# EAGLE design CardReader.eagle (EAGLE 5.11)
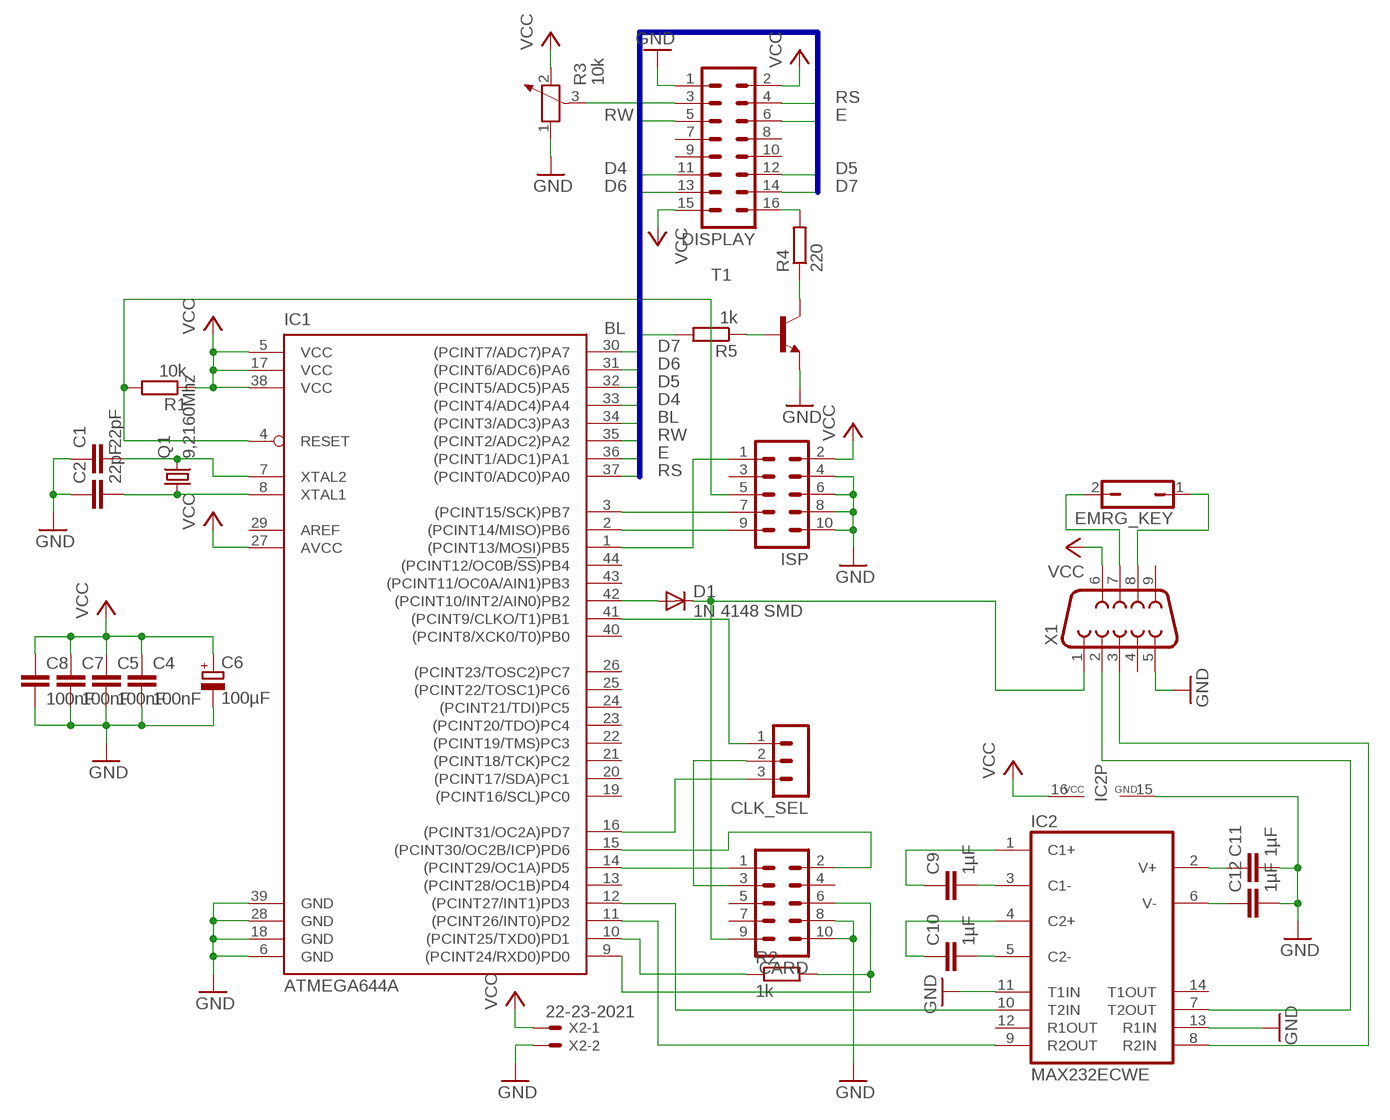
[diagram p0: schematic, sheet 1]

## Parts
C1  22pF  C-EUC0603  [C0603]
C2  22pF  C-EUC0603  [C0603]
C4  100nF  C-EUC0603  [C0603]
C5  100nF  C-EUC0603  [C0603]
C6  100µF  CPOL-EUE2.5-7  [E2,5-7]
C7  100nF  C-EUC0603  [C0603]
C8  100nF  C-EUC0603  [C0603]
C9  1µF  C-EUC0603  [C0603]
C10  1µF  C-EUC0603  [C0603]
C11  1µF  C-EUC0603  [C0603]
C12  1µF  C-EUC0603  [C0603]
CARD  ML10  [ML10]
CLK_SEL  MA03-1  [MA03-1]
D1  1N 4148 SMD  DIODE-MINIMELF  [MINIMELF]
DISPLAY  ML16  [ML16]
EMRG_KEY  JP1Q  [JP1]
IC1  ATMEGA644A  [TQFP44]
IC2  MAX232ECWE  [SO16L]
ISP  ML10  [ML10]
Q1  9,2160Mhz  CRYSTALHC49U-V  [HC49U-V]
R1  10k  R-EU_R0603  [R0603]
R2  1k  R-EU_R0603  [R0603]
R3  10k  POTENTIOMETER_PT-10S  [PT-10S]
R4  220  R-EU_R0603  [R0603]
R5  1k  R-EU_R0603  [R0603]
T1  -NPN-TO92  [TO92]
X1  F09H  [F09H]
X2  22-23-2021  [22-23-2021]

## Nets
BL: IC1.34((PCINT3/ADC3)PA3) R5.2
D4: DISPLAY.11 IC1.33((PCINT4/ADC4)PA4)
D5: DISPLAY.12 IC1.32((PCINT5/ADC5)PA5)
D6: DISPLAY.13 IC1.31((PCINT6/ADC6)PA6)
D7: DISPLAY.14 IC1.30((PCINT7/ADC7)PA7)
E: DISPLAY.6 IC1.36((PCINT1/ADC1)PA1)
GND: C1.1 C2.1 C4.2 C5.2 C6.- C7.2 C8.2 C11.2 C12.2 CARD.8 CARD.10 DISPLAY.1 IC1.6(GND) IC1.18(GND) IC1.28(GND) IC1.39(GND) IC2.11(T1IN) IC2.13(R1IN) IC2.15(GND) ISP.4 ISP.6 ISP.8 ISP.10 R3.1 T1.1(E) X1.5 X2.2
N$1: IC1.4(RESET) ISP.5 R1.2
N$2: C9.2 IC2.3(C1-)
N$3: C9.1 IC2.1(C1+)
N$4: C2.2 IC1.8(XTAL1) Q1.1
N$5: C1.2 IC1.7(XTAL2) Q1.2
N$6: C10.2 IC2.5(C2-)
N$7: C10.1 IC2.4(C2+)
N$8: C11.1 IC2.2(V+)
N$9: C12.1 IC2.6(V-)
N$10: IC1.1((PCINT13/MOSI)PB5) ISP.1
N$11: IC1.3((PCINT15/SCK)PB7) ISP.7
N$12: IC1.2((PCINT14/MISO)PB6) ISP.9
N$13: CARD.9 D1.C X1.1
N$14: CLK_SEL.1 IC1.41((PCINT9/CLKO/T1)PB1)
N$15: CARD.1 IC1.14((PCINT29/OC1A)PD5)
N$16: CARD.2 IC1.15((PCINT30/OC2B/ICP)PD6)
N$17: D1.A IC1.42((PCINT10/INT2/AIN0)PB2)
N$18: CARD.6 IC1.9((PCINT24/RXD0)PD0) R2.2
N$19: CLK_SEL.3 IC1.16((PCINT31/OC2A)PD7)
N$20: CARD.3 CLK_SEL.2
N$21: DISPLAY.3 R3.3
N$22: R5.1 T1.2(B)
N$23: R4.1 T1.3(C)
N$24: DISPLAY.16 R4.2
N$25: IC1.11((PCINT26/INT0)PD2) IC2.9(R2OUT)
N$26: IC1.12((PCINT27/INT1)PD3) IC2.10(T2IN)
N$27: EMRG_KEY.1 X1.8
N$28: EMRG_KEY.2 X1.7
N$29: IC2.8(R2IN) X1.3
N$30: IC2.7(T2OUT) X1.2
N$31: IC1.10((PCINT25/TXD0)PD1) R2.1
RS: DISPLAY.4 IC1.37((PCINT0/ADC0)PA0)
RW: DISPLAY.5 IC1.35((PCINT2/ADC2)PA2)
VCC: C4.1 C5.1 C6.+ C7.1 C8.1 DISPLAY.2 DISPLAY.15 IC1.5(VCC) IC1.17(VCC) IC1.27(AVCC) IC1.38(VCC) IC2.16(VCC) ISP.2 R1.1 R3.2 X1.6 X2.1
Unconnected: CARD.4 CARD.5 CARD.7 DISPLAY.7 DISPLAY.8 DISPLAY.9 DISPLAY.10 IC1.13((PCINT28/OC1B)PD4) IC1.19((PCINT16/SCL)PC0) IC1.20((PCINT17/SDA)PC1) IC1.21((PCINT18/TCK)PC2) IC1.22((PCINT19/TMS)PC3) IC1.23((PCINT20/TDO)PC4) IC1.24((PCINT21/TDI)PC5) IC1.25((PCINT22/TOSC1)PC6) IC1.26((PCINT23/TOSC2)PC7) IC1.29(AREF) IC1.40((PCINT8/XCK0/T0)PB0) IC1.43((PCINT11/OC0A/AIN1)PB3) IC1.44((PCINT12/OC0B/!SS!)PB4) IC2.12(R1OUT) IC2.14(T1OUT) ISP.3 X1.4 X1.9

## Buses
DISPLAY:D[0..7],E,RS,RW,BL

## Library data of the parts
C1 C2 C4 C5 C7-C12 = rcl:C-EU: CAPACITOR, European symbol
C6 = rcl:CPOL-EU: POLARIZED CAPACITOR, European symbol
CARD ISP = con-harting-ml:ML10: HARTING; OC_FARNELL: unknown; OC_NEWARK: unknown
CLK_SEL = con-lstb:MA03-1: PIN HEADER; OC_FARNELL: unknown; OC_NEWARK: unknown
D1 = diode:DIODE-: DIODE
DISPLAY = con-harting-ml:ML16: HARTING; OC_FARNELL: unknown; OC_NEWARK: unknown
EMRG_KEY = jumper:JP1Q: JUMPER
IC1 = atmel:ATMEGA644: 8-bit Microcontroller with 64K Bytes In-System Programmable Flash Source: http://www.atmel.com/dyn/resources/prod_documents/doc2593.pdf; MPN: ATMEGA644PV-10AU; OC_FARNELL: 1455123; OC_NEWARK: 58M3748
IC2 = maxim:MAX232ECWE: RS232 TRANSEIVER; MF: MAXIM; MPN: MAX232ECWE+; OC_FARNELL: 9724435; OC_NEWARK: 67K4440
Q1 = crystal:CRYSTAL: CRYSTAL; OC_FARNELL: 1666969; OC_NEWARK: unknown
R1 R2 R4 R5 = rcl:R-EU_: RESISTOR, European symbol
R3 = rcl:POTENTIOMETER_: Potentiometer
T1 = transistor:*-NPN-: NPN Transistror BF959 corrected 2008.03.06
X1 = con-subd:F09: SUB-D; OC_FARNELL: unknown; OC_NEWARK: unknown
X2 = con-molex:22-23-2021: .100" (2.54mm) Center Header - 2 Pin; MF: MOLEX; MPN: 22-23-2021; OC_FARNELL: 1462926; OC_NEWARK: 25C3832

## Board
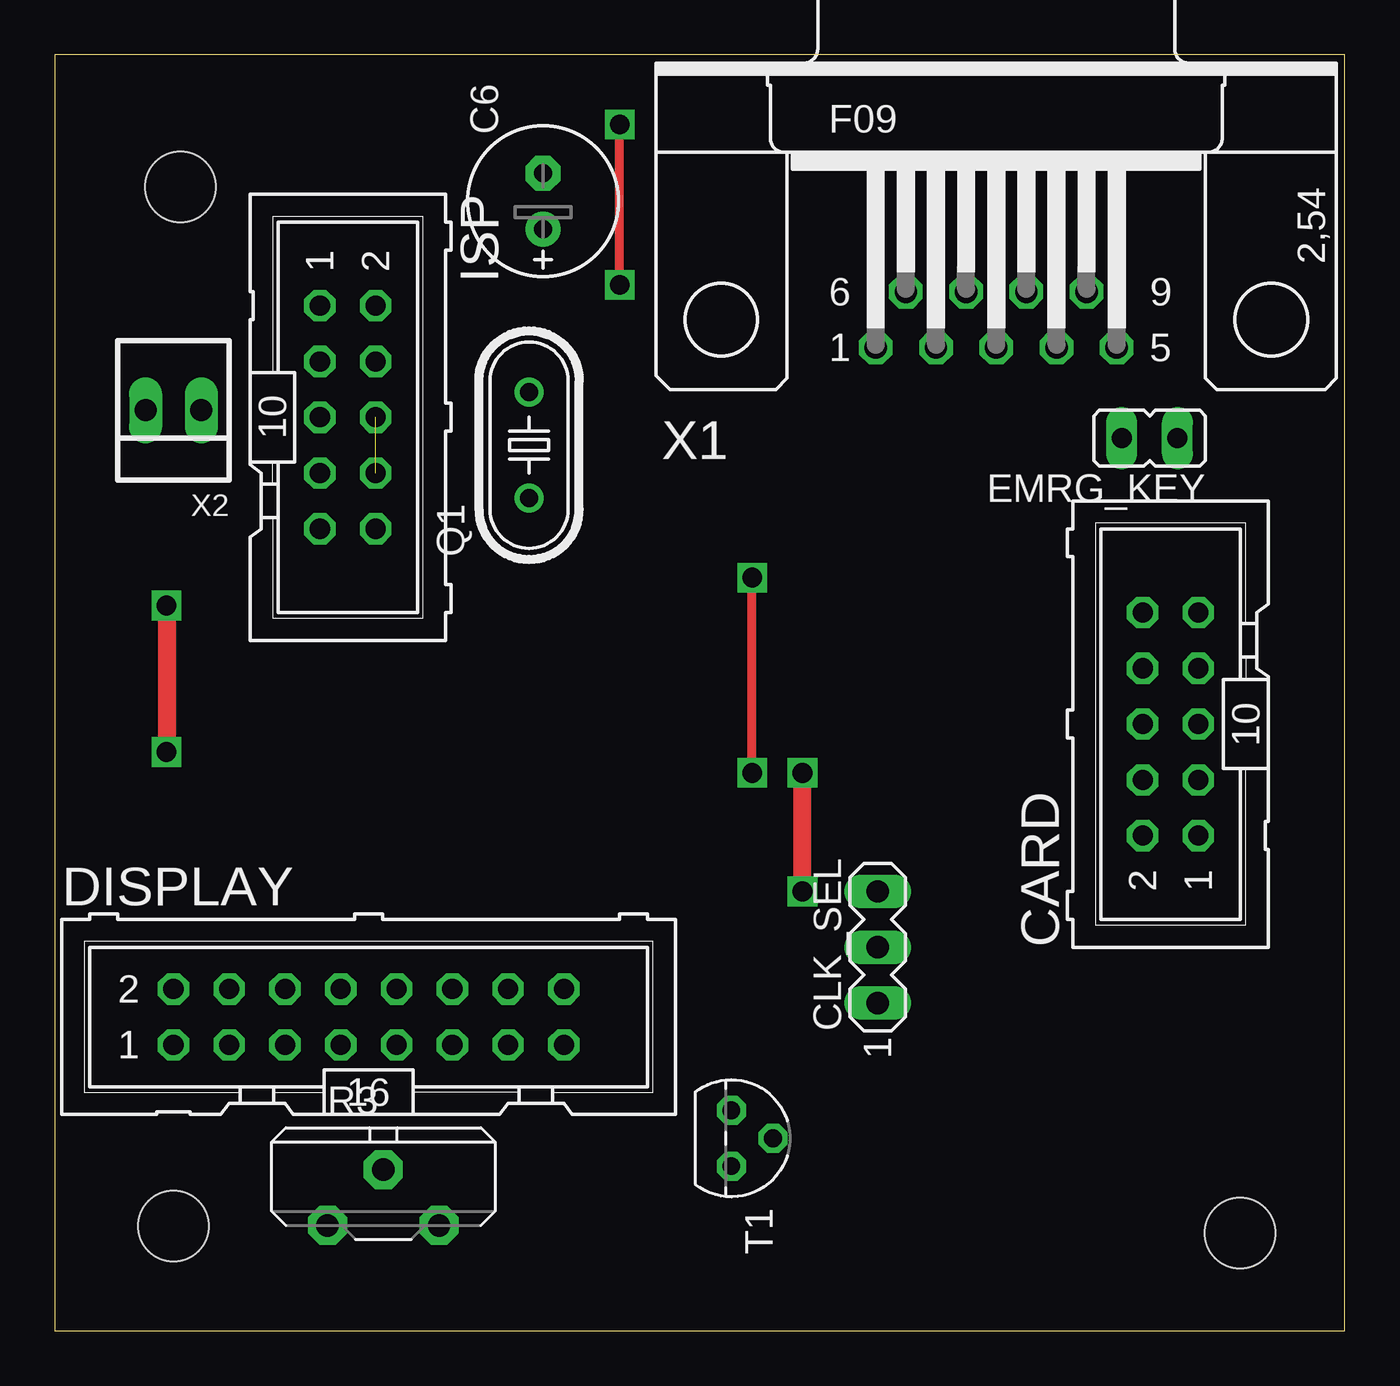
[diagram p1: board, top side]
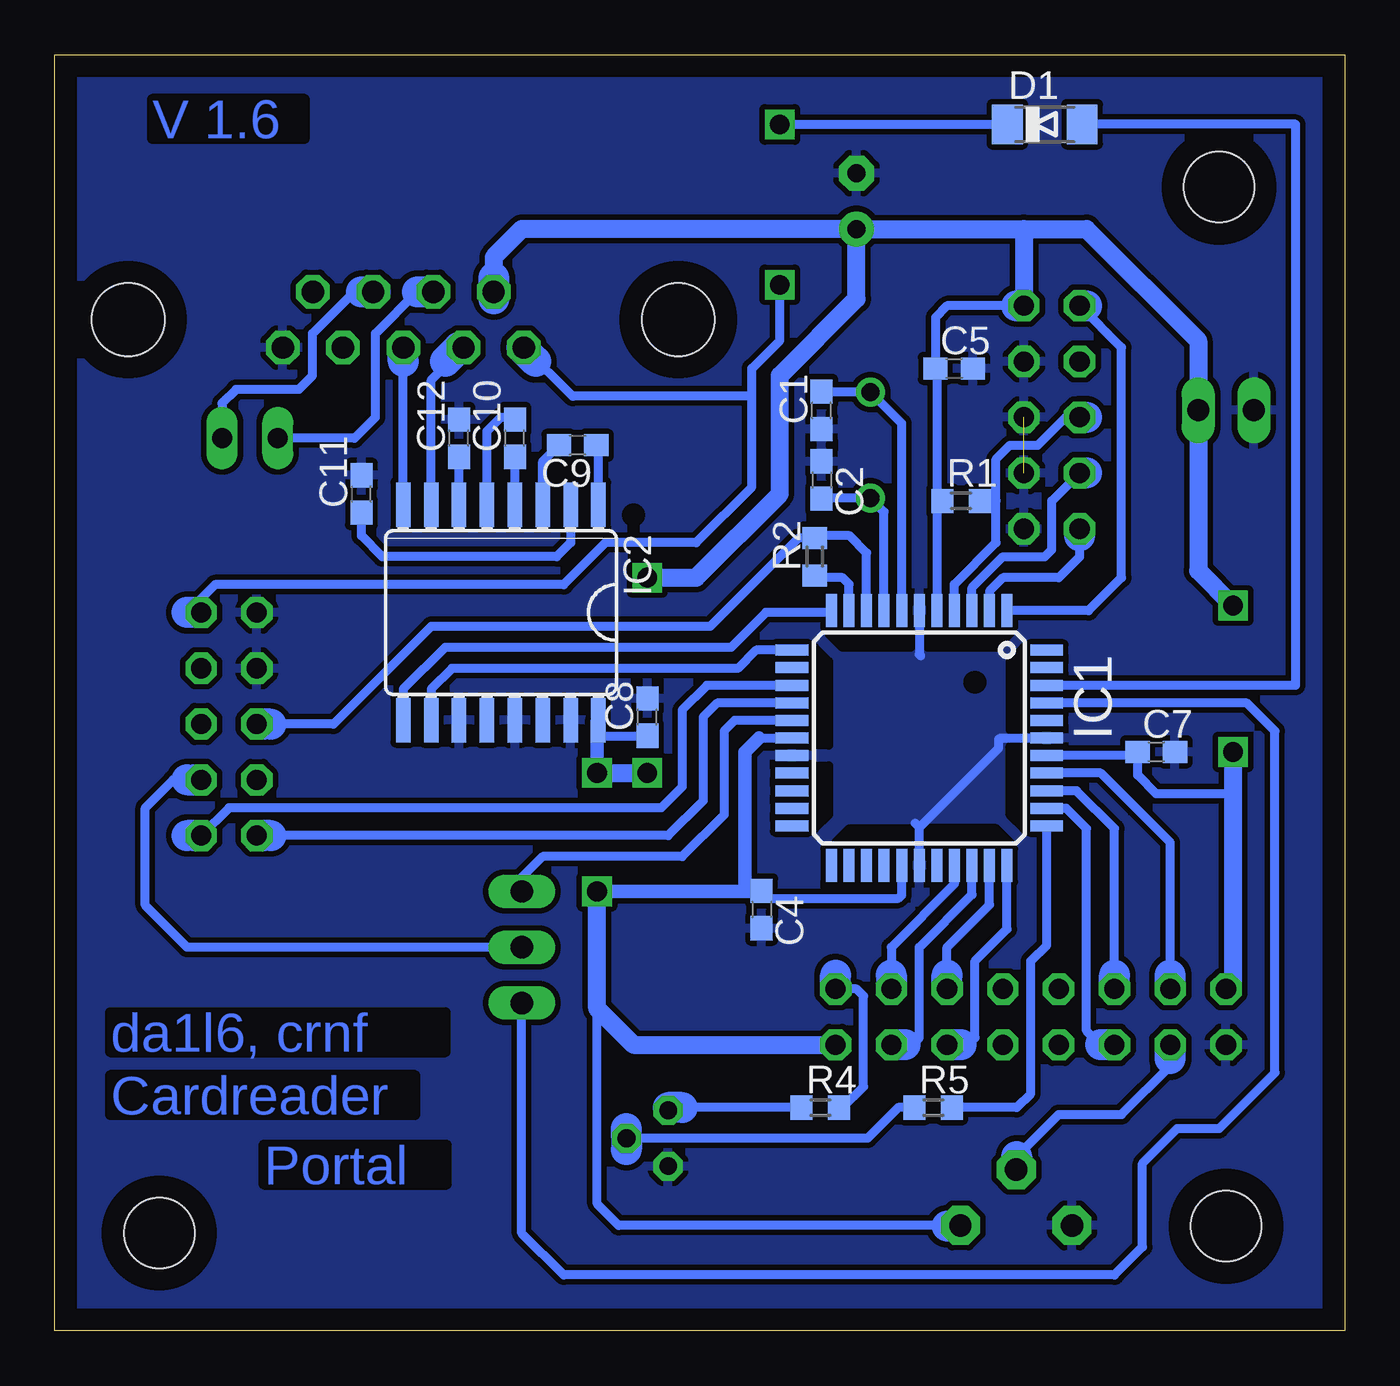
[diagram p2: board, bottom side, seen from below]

Size 58.73 x 58.09 mm. Coordinates in mm from the lower left corner, seen from the top.
Outline: 0,0 58.73,0 58.73,58.09 0,58.09 0,0
Copper layers (1*16): Top 0.035mm / dielectric 1.5mm / Bottom 0.035mm
Design rules "Bilex DRU": minimum track width 10mil, minimum drill 24mil, track to track 10mil, track to pad 10mil, pad to pad 10mil, via to via 10mil, smd to smd 10mil, copper to edge 40mil, drill to drill 8mil, minimum pad ring 10mil, minimum via ring 8mil, stop-mask expansion 4mil, vias tented up to drill 0mil, thermal gap 10mil
Holes 3.2 mm at 5.71,52.07 53.98,4.45 5.4,4.76
bRestrict: area 16.5,29.2 to 17.1,29.8; area 32.1,36.8 to 32.7,37.5; area 23.5,26.7 to 24.1,31.1; area 23.5,22.9 to 24.1,25.7; area 19.7,22.2 to 23.2,22.9; area 15.2,22.2 to 19,22.9; area 14.6,22.9 to 15.2,26.6; area 14.6,27.4 to 15.2,31.1; area 15.2,31.1 to 19,31.8; area 19.7,31.1 to 23.5,31.8

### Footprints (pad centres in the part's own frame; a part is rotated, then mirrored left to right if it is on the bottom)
C0603 = smd 1.1 x 1: 1 -0.85,0; 2 0.85,0
E2,5-7 = drill 0.813 pad 1.6 round: + -1.27,0 | drill 0.813 pad 1.6 octagon: - 1.27,0
ML10 = drill 0.914 octagon: 1 -5.08,-1.27; 2 -5.08,1.27; 3 -2.54,-1.27; 4 -2.54,1.27; 5 0,-1.27; 6 0,1.27; 7 2.54,-1.27; 8 2.54,1.27; 9 5.08,-1.27; 10 5.08,1.27
MA03-1 = drill 1.016 long: 1 -2.54,0; 2 0,0; 3 2.54,0
MINIMELF = smd 1.4 x 1.8: A 1.7,0; C -1.7,0
ML16 = drill 0.914 octagon: 1 -8.89,-1.27; 2 -8.89,1.27; 3 -6.35,-1.27; 4 -6.35,1.27; 5 -3.81,-1.27; 6 -3.81,1.27; 7 -1.27,-1.27; 8 -1.27,1.27; 9 1.27,-1.27; 10 1.27,1.27; 11 3.81,-1.27; 12 3.81,1.27; 13 6.35,-1.27; 14 6.35,1.27; 15 8.89,-1.27; 16 8.89,1.27
JP1 = drill 0.914 long: 1 0,-1.27; 2 0,1.27
TQFP44 = smd 1.5 x 0.5: 1 -5.8,4; 2 -5.8,3.2; 3 -5.8,2.4; 4 -5.8,1.6; 5 -5.8,0.8; 6 -5.8,0; 7 -5.8,-0.8; 8 -5.8,-1.6; 9 -5.8,-2.4; 10 -5.8,-3.2; 11 -5.8,-4; 23 5.8,-4; 24 5.8,-3.2; 25 5.8,-2.4; 26 5.8,-1.6; 27 5.8,-0.8; 28 5.8,0; 29 5.8,0.8; 30 5.8,1.6; 31 5.8,2.4; 32 5.8,3.2; 33 5.8,4 | smd 0.5 x 1.5: 12 -4,-5.8; 13 -3.2,-5.8; 14 -2.4,-5.8; 15 -1.6,-5.8; 16 -0.8,-5.8; 17 0,-5.8; 18 0.8,-5.8; 19 1.6,-5.8; 20 2.4,-5.8; 21 3.2,-5.8; 22 4,-5.8; 34 4,5.8; 35 3.2,5.8; 36 2.4,5.8; 37 1.6,5.8; 38 0.8,5.8; 39 0,5.8; 40 -0.8,5.8; 41 -1.6,5.8; 42 -2.4,5.8; 43 -3.2,5.8; 44 -4,5.8
SO16L = smd 0.66 x 2.032: 1 -4.445,-4.902; 2 -3.175,-4.902; 3 -1.905,-4.902; 4 -0.635,-4.902; 5 0.635,-4.902; 6 1.905,-4.902; 7 3.175,-4.902; 8 4.445,-4.902; 9 4.445,4.902; 10 3.175,4.902; 11 1.905,4.902; 12 0.635,4.902; 13 -0.635,4.902; 14 -1.905,4.902; 15 -3.175,4.902; 16 -4.445,4.902
HC49U-V = drill 0.813 round: 1 -2.413,0; 2 2.413,0
R0603 = smd 1 x 1.1: 1 -0.85,0; 2 0.85,0
PT-10S = drill 1.016 pad 1.778 octagon: 1 -2.54,-1.27; 2 2.54,-1.27; 3 0,1.27
TO92 = drill 0.813 octagon: 1 1.27,0; 2 0,1.905; 3 -1.27,0
F09H = drill 1.016 octagon: 1 -5.486,-1.27; 2 -2.743,-1.27; 3 0,-1.27; 4 2.743,-1.27; 5 5.486,-1.27; 6 -4.115,1.27; 7 -1.372,1.27; 8 1.372,1.27; 9 4.115,1.27 | hole 3.302: -12.522,0; 12.522,0
22-23-2021 = drill 1 long: 1 -1.27,0; 2 1.27,0

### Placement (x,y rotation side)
C1  23.81,41.91 90 bottom
C2  23.81,38.73 270 bottom
C4  26.54,19.18 270 bottom
C5  17.78,43.81 0 bottom
C6  22.23,51.44 90 top
C7  8.57,26.35 0 bottom
C8  31.75,27.94 90 bottom
C9  34.92,40.32 180 bottom
C10  37.78,40.64 90 bottom
C11  44.77,38.1 90 bottom
C12  40.32,40.64 90 bottom
CARD  50.8,27.62 90 top
CLK_SEL  37.47,17.46 90 top
D1  13.65,54.93 0 bottom
DISPLAY  14.29,14.29 0 top
EMRG_KEY  49.85,40.64 90 top
IC1  19.37,26.99 270 bottom
IC2  38.42,32.7 180 bottom
ISP  13.34,41.59 270 top
Q1  21.59,40.32 90 top
R1  17.46,37.78 0 bottom
R2  24.13,35.24 90 bottom
R3  14.95,6.06 0 top
R4  23.88,10.16 0 bottom
R5  18.73,10.16 0 bottom
T1  30.8,8.76 270 top
X1  42.86,46.04 0 top
X2  5.4,41.91 180 top

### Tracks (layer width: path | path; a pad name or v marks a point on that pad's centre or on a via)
BL
  Bottom 0.406: IC1.34 13.57,17.55 14.29,16.83 14.29,10.79 14.92,10.16 R5.2
D4
  Bottom 0.406: IC1.33 15.37,18.29 16.83,16.83 16.83,13.34 17.14,13.02 17.46,13.02 17.78,13.02
  Bottom 1.422: 17.78,13.02 DISPLAY.11 17.46,13.02
D5
  Bottom 0.406: IC1.32 16.17,19.39 18.1,17.46 18.1,16.19
  Bottom 1.422: DISPLAY.12 18.1,16.19
D6
  Bottom 0.406: IC1.31 16.97,19.86 19.37,17.46 19.37,13.34 19.68,13.02 20,13.02
  Bottom 1.422: 20,13.02 DISPLAY.13
D7
  Bottom 0.406: IC1.30 17.77,20.33 20.64,17.46 20.64,16.19
  Bottom 1.422: 20.64,16.19 DISPLAY.14
E
  Bottom 0.406: IC1.36 12.21,24.59 10.48,22.86 10.48,16.19
  Bottom 1.422: DISPLAY.6 10.48,16.19
GND  (1 unrouted)
  Bottom 0.406: IC1.39 15.68,26.99 15.75,26.92 15.75,26.54 19.37,22.92 | IC1.6 19.37,30.8 19.3,30.73 | IC1.28 19.37,22.92 | 19.37,22.92 19.56,23.11
  pour Bottom: 0,58.1 58.74,58.1 58.74,0 0,0
N$1
  Bottom 0.406: IC1.4 17.77,33.98 15.88,35.88 15.88,37.78 | 15.88,37.78 R1.2 | 15.88,37.78 15.88,39.69 15.24,40.32 13.97,40.32 12.7,41.59 ISP.5
  Bottom 1.422: ISP.5 11.75,41.59
N$2
  Bottom 0.406: IC2.3 36.51,39.59 C9.2
N$3
  Bottom 0.406: IC2.1 33.97,40.22 C9.1
N$4
  Bottom 0.406: IC1.8 20.97,37.29 Q1.1 23.79,37.91 C2.2
N$5
  Bottom 0.406: IC1.7 20.17,41.31 Q1.2 23.79,42.74 C1.2
N$6
  Bottom 0.406: IC2.5 39.05,40.96 38.42,41.59 37.88,41.59 C10.2
N$7
  Bottom 0.406: IC2.4 C10.1
N$8
  Bottom 0.406: IC2.2 35.24,35.88 35.88,35.24 43.81,35.24 44.77,36.2 C11.1
N$9
  Bottom 0.406: IC2.6 C12.1
N$10
  Bottom 0.406: IC1.1 11.66,32.79 10.16,34.29 10.16,44.77 ISP.1
  Bottom 1.422: ISP.1 11.75,46.67
N$11
  Bottom 0.406: IC1.3 16.97,33.83 15.56,35.24 13.65,35.24 13.34,35.56 13.34,37.78 ISP.7
  Bottom 1.422: ISP.7 11.75,39.05
N$12
  Bottom 0.406: IC1.2 16.17,33.68 15.56,34.29 13.02,34.29 12.06,35.24 12.06,36.2
  Bottom 1.422: 12.06,36.2 ISP.9
N$13  (via drill 0.9)
  Top 0.406: v25.72,47.62 v25.72,54.93
  Bottom 0.406: X1.1 35.15,42.55 26.99,42.55 | CARD.9 52.07,33.34 51.44,33.97 35.56,33.97 33.66,35.88 29.53,35.88 26.99,38.42 26.99,42.55 | v25.72,47.62 25.72,45.09 26.99,43.81 26.99,42.55 | v25.72,54.93 D1.C
  Bottom 1.422: 52.39,32.7 CARD.9 52.7,32.7
N$14
  Bottom 0.406: CLK_SEL.1 37.47,4.45 35.56,2.54 10.48,2.54 9.21,3.81 9.21,7.62 7.62,9.21 5.71,9.21 3.17,11.75 3.17,27.3 4.45,28.57 13.55,28.57 IC1.41
N$15
  Bottom 0.406: IC1.14 29.03,29.39 30.16,28.26 30.16,24.77 31.11,23.81 50.8,23.81 CARD.1
  Bottom 1.422: 52.39,22.54 CARD.1 52.7,22.54
N$16
  Bottom 0.406: IC1.15 25.18,28.57 28.57,28.57 29.21,27.94 29.21,24.13 30.8,22.54 48.9,22.54 49.21,22.54
  Bottom 1.422: 49.21,22.54 CARD.2 48.9,22.54
N$17
  Bottom 0.406: IC1.42 2.22,29.39 2.22,54.93 D1.A
N$18
  Bottom 0.406: IC1.9 21.77,35.42 22.54,36.2 24.03,36.2 R2.2 24.87,36.09 28.89,32.07 41.59,32.07 46.04,27.62 48.9,27.62 49.21,27.62
  Bottom 1.422: 49.21,27.62 CARD.6 48.9,27.62
N$19
  Bottom 0.406: IC1.16 27.77,27.79 28.26,27.3 28.26,23.5 30.16,21.59 36.51,21.59 37.47,20.64 CLK_SEL.3
N$20
  Bottom 0.406: 52.39,25.08 52.7,25.08 53.34,25.08 54.61,23.81 54.61,19.37 52.7,17.46 CLK_SEL.2
  Bottom 1.422: 52.39,25.08 CARD.3 52.7,25.08
N$21
  Bottom 0.406: R3.3 14.92,7.94 13.02,9.84 10.16,9.84 7.94,12.06 7.94,12.38
  Bottom 1.422: 7.94,12.38 DISPLAY.3 | 14.92,7.94 14.92,7.3
N$22
  Bottom 0.406: R5.1 20.32,10.16 21.72,8.76 T1.2
N$23
  Bottom 0.406: R4.1 30.16,10.16 30.67,10.16 T1.3
  Bottom 1.422: 30.16,10.16 30.8,10.16
N$24
  Bottom 0.406: R4.2 22.86,10.16 21.91,11.11 21.91,15.24 22.23,15.56 DISPLAY.16
  Bottom 1.422: DISPLAY.16 23.18,16.19
N$25
  Bottom 0.406: IC2.9 42.86,29.21 40.96,31.11 27.94,31.11 26.35,32.7 23.45,32.7 IC1.11
N$26
  Bottom 0.406: IC2.10 41.59,29.21 40.64,30.16 27.62,30.16 26.8,30.99 IC1.12
N$27
  Bottom 0.406: X1.8 44.77,47.31 45.09,47.31 46.99,45.4 46.99,43.5 47.62,42.86 50.48,42.86 51.12,42.23 EMRG_KEY.1
  Bottom 1.422: 44.77,47.31 44.13,47.31
N$28
  Bottom 0.406: 41.59,47.31 X1.7 | 42.23,47.31 44.13,45.4 44.13,41.59 45.09,40.64 EMRG_KEY.2
  Bottom 1.422: 42.23,47.31 41.59,47.31
N$29
  Bottom 0.406: IC2.8 42.86,44.13
  Bottom 1.422: 42.86,44.13 X1.3
N$30
  Bottom 0.406: IC2.7 41.59,43.29 X1.2
N$31
  Bottom 0.406: IC1.10 22.57,34 22.86,34.29 24.03,34.29 R2.1
N$32
  Bottom 1.422: 17.46,4.76 18.1,4.76
N$33
  Bottom 1.422: 32.7,9.21 32.7,8.89 32.7,8.26
N$34
  Bottom 1.422: 40.32,44.77 40.96,44.13
N$35
  Bottom 1.422: 37.47,44.77 36.83,44.13
N$36
  Bottom 1.422: 38.73,46.99 38.73,47.94
RS
  Bottom 0.406: IC1.37 11.1,25.39 7.94,22.23 7.94,16.19
  Bottom 1.422: DISPLAY.4 7.94,16.19
RW
  Bottom 0.406: IC1.35 12.68,23.79 11.75,22.86 11.75,13.65 11.11,13.02
  Bottom 1.422: DISPLAY.5 11.11,13.02
VCC  (via drill 0.9, 0.9 pad 1.27)
  Top 0.406: v31.75,25.4 v31.75,34.29
  Top 0.813: v5.08,33.02 v5.08,26.35 | v34.04,20 v34.04,25.4
  Bottom 0.406: IC2.16 33.97,26.99 33.87,27.09 C8.1 | IC1.38 9.59,26.19 C7.1 9.42,25.3 8.57,24.45 5.08,24.45 | 18.57,37.78 18.57,43.75 C5.1 18.63,46.14 18.1,46.67 14.92,46.67 | 18.57,37.78 IC1.5 | 18.57,37.78 R1.1 | 26.67,26.99 IC1.17 | IC1.27 20.17,19.84 20.32,19.68 26.2,19.68 C4.1 | 34.04,14.67 34.04,5.78 33.05,4.79 R3.2
  Bottom 0.61: 26.67,26.99 27.3,26.35 27.3,20 | v34.04,25.4 34.04,27.74 IC2.16 | v34.04,20 27.3,20 | 27.3,20 26.57,20 C4.1
  Bottom 0.813: X1.6 38.75,48.88 37.47,50.16 C6.+ | C6.+ 14.61,50.16 | 14.61,50.16 ISP.2 | v5.08,33.02 6.67,34.61 X2.1 6.67,45.09 11.75,50.16 14.61,50.16 | v5.08,26.35 5.08,24.45 5.08,15.88 DISPLAY.2 | C6.+ 22.23,46.99 25.72,43.5 25.72,38.1 29.53,34.29 v31.75,34.29 | v34.04,25.4 v31.75,25.4 | DISPLAY.15 32.38,13.02 34.04,14.67 v34.04,20
  Bottom 1.422: ISP.2 14.92,46.67

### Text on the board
Bottom: V 1.6 | da1l6, crnf | Cardreader | Portal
